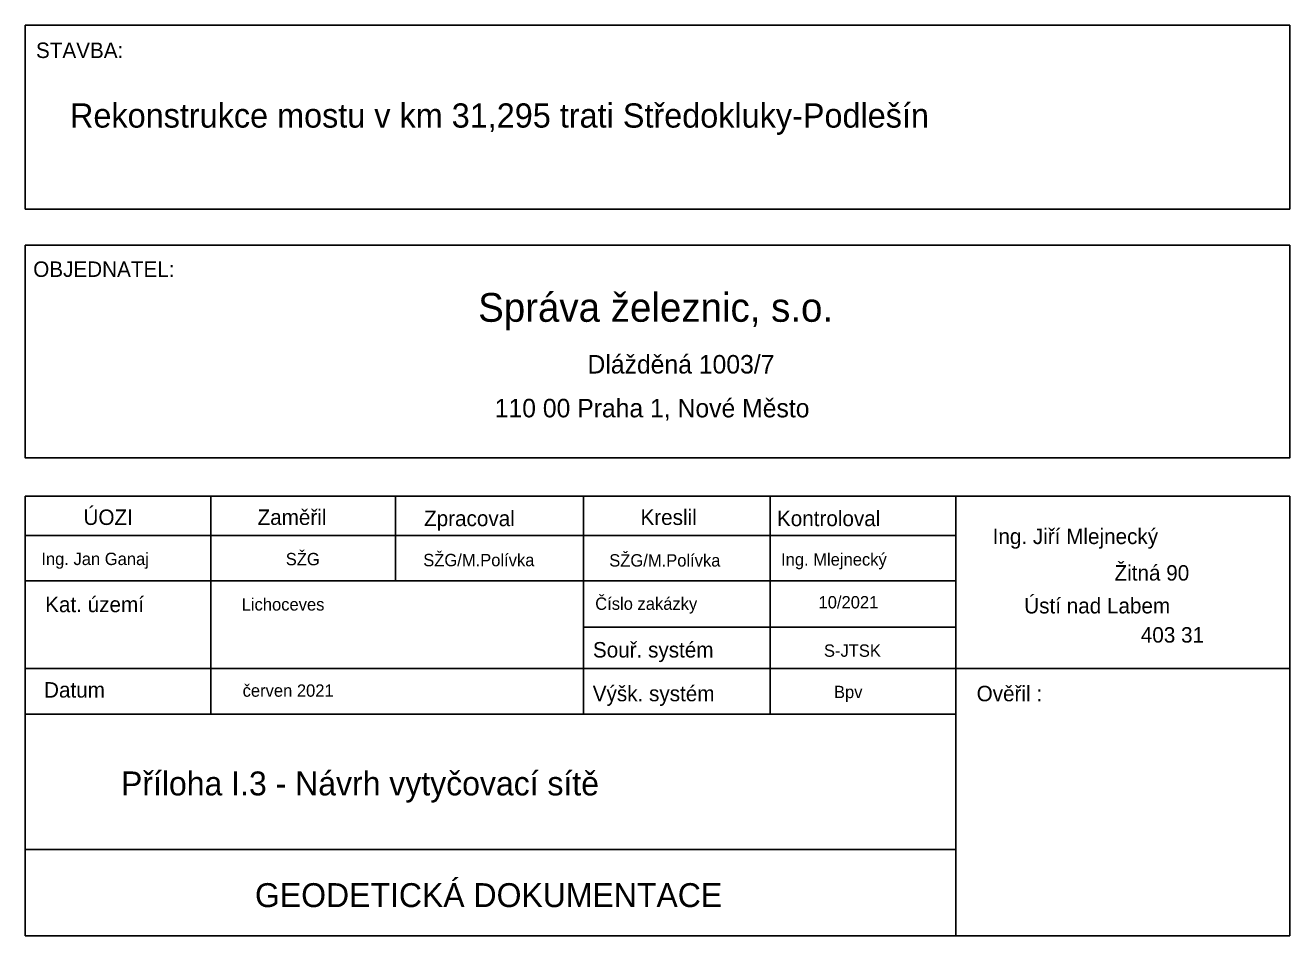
# Model space of a CAD drawing. Extents: x -879530 to -879371, y -1019242 to -1019127.
import ezdxf

# ---------------------------------------------------------------- set-up
doc = ezdxf.new("R2010")
doc.units = 0
doc.layers.add('tabulka', color=7, linetype='Continuous')

msp = doc.modelspace()

# ---------------------------------------------------------------- linework, layer by layer
at = {"layer": 'tabulka'}
for p, q in [((-879530.09, -1019186.45), (-879371.44, -1019186.45)), ((-879506.8, -1019186.45), (-879506.8, -1019213.77)), ((-879483.66, -1019186.45), (-879483.66, -1019197.07)), ((-879460.06, -1019186.45), (-879460.06, -1019213.77)), ((-879436.61, -1019186.45), (-879436.61, -1019213.77)), ((-879413.31, -1019241.58), (-879413.31, -1019186.45)), ((-879530.09, -1019191.36), (-879413.31, -1019191.36)), ((-879530.09, -1019197.07), (-879413.31, -1019197.07)), ((-879460.06, -1019202.88), (-879413.31, -1019202.88)), ((-879530.09, -1019208.07), (-879371.44, -1019208.07)), ((-879530.09, -1019213.77), (-879413.31, -1019213.77)), ((-879530.09, -1019230.76), (-879413.31, -1019230.76))]:
    msp.add_line(p, q, dxfattribs=at)
for points in [[(-879530.09, -1019127.36), (-879371.44, -1019127.36), (-879371.44, -1019150.43), (-879530.09, -1019150.43)], [(-879530.09, -1019154.95), (-879371.44, -1019154.95), (-879371.44, -1019181.64), (-879530.09, -1019181.64)]]:
    msp.add_lwpolyline(points, close=True, dxfattribs=at)
msp.add_lwpolyline([(-879371.44, -1019186.45), (-879371.44, -1019241.58), (-879530.09, -1019241.58), (-879530.09, -1019186.45)], dxfattribs=at)

# ---------------------------------------------------------------- texts
for s, height, p in [('STAVBA:', 1.94, (-879528.75, -1019131.47)), ('Rekonstrukce mostu v km 31,295 trati Středokluky-Podlešín', 3.04, (-879524.48, -1019140.2)), ('OBJEDNATEL:', 1.94, (-879529.1, -1019158.93)), ('Správa železnic, s.o.', 3.61, (-879473.27, -1019164.56)), ('Dlážděná 1003/7', 2.32, (-879459.55, -1019171.05)), ('110 00 Praha 1, Nové Město', 2.32, (-879471.19, -1019176.55)), ('ÚOZI', 1.94, (-879522.79, -1019190.05)), ('Zaměřil', 1.94, (-879500.95, -1019190.05)), ('Zpracoval', 1.94, (-879480.06, -1019190.2)), ('Kreslil', 1.94, (-879452.9, -1019190.05)), ('Kontroloval', 1.94, (-879435.78, -1019190.2)), ('Ing. Jiří Mlejnecký', 1.94, (-879408.71, -1019192.45)), ('Ing. Jan Ganaj', 1.552, (-879528.08, -1019195.08)), ('SŽG', 1.552, (-879497.41, -1019195.11)), ('SŽG/M.Polívka', 1.552, (-879480.16, -1019195.23)), ('SŽG/M.Polívka', 1.552, (-879456.82, -1019195.27)), ('Ing. Mlejnecký', 1.552, (-879435.26, -1019195.15)), ('Žitná 90', 1.94, (-879393.42, -1019197.03)), ('Kat. území', 1.94, (-879527.6, -1019200.99)), ('Lichoceves', 1.552, (-879502.94, -1019200.79)), ('Číslo zakázky', 1.552, (-879458.58, -1019200.7)), ('10/2021', 1.552, (-879430.56, -1019200.52)), ('Ústí nad Labem', 1.94, (-879404.75, -1019201.15)), ('403 31', 1.94, (-879390.12, -1019204.81)), ('Souř. systém', 1.94, (-879458.87, -1019206.68)), ('S-JTSK', 1.552, (-879429.88, -1019206.59)), ('Datum', 1.94, (-879527.74, -1019211.71)), ('červen 2021', 1.552, (-879502.82, -1019211.6)), ('Výšk. systém', 1.94, (-879458.89, -1019212.17)), ('Bpv', 1.552, (-879428.62, -1019211.78)), ('Ověřil :', 1.94, (-879410.72, -1019212.17)), ('Příloha I.3 - Návrh vytyčovací sítě', 3, (-879518.08, -1019223.98)), ('GEODETICKÁ DOKUMENTACE ', 3, (-879501.27, -1019237.99))]:
    msp.add_text(s, height=height, dxfattribs=at).set_placement(p)

doc.saveas('drawing.dxf')
